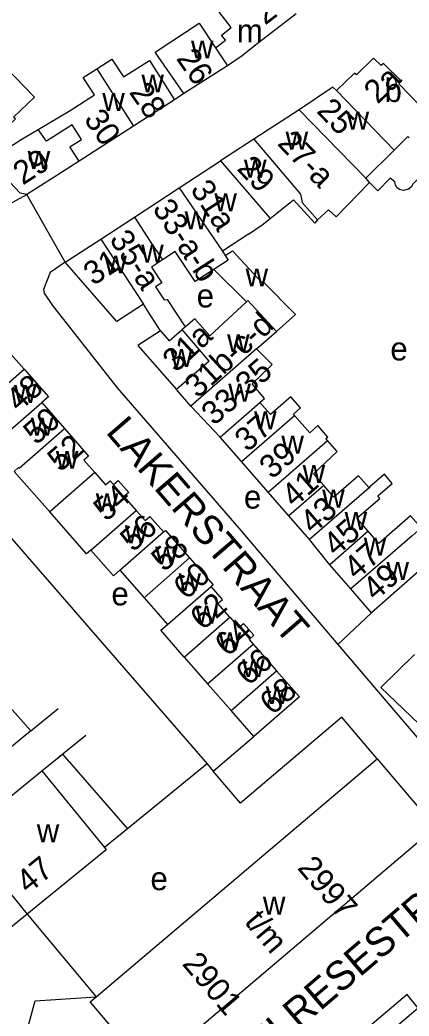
# Model space of a CAD drawing. Extents: x 161775 to 163181, y 382878 to 383925.
# Drawn here: x 162245.9 to 162312.7, y 383208.3 to 383379.1 of the extents above; entities that cross this region are included whole.
import ezdxf

# ---------------------------------------------------------------- set-up
doc = ezdxf.new("R2010")
doc.units = 0
for name, color, linetype in [('BLT_Basislijn', 7, 'Continuous'), ('BLT_Bebouwing', 7, 'Continuous'), ('BLT_Centroide', 7, 'Continuous'), ('BLT_Huisnummer', 7, 'Continuous'), ('BLT_Huisnummer_ tussenligend', 7, 'Continuous'), ('BLT_Huisnummer_reeks', 7, 'Continuous'), ('BLT_Onderdoorgang_en_onderverdeling', 7, 'Continuous'), ('BLT_Onderverdeling_panden', 7, 'Continuous'), ('BLT_Straatnaam', 7, 'Continuous'), ('BLT_Vlakafsluiter', 7, 'Continuous')]:
    doc.layers.add(name, color=color, linetype=linetype)

msp = doc.modelspace()

# ---------------------------------------------------------------- linework, layer by layer
at = {"layer": 'BLT_Basislijn'}
for p, q in [((162274.06, 383366.49), (162272.47, 383365.4)), ((162300.43, 383272.05), (162306.21, 383277.49)), ((162247.8, 383257.21), (162252.5, 383261.05)), ((162252.51, 383252.64), (162257.22, 383256.48)), ((162278.02, 383251.56), (162264.39, 383240.46)), ((162278.02, 383251.56), (162279.09, 383250.32)), ((162264.39, 383240.46), (162260.42, 383237.22)), ((162247.18, 383225.8), (162259, 383211.62)), ((162312.32, 383212.02), (162272.82, 383178.64)), ((162314.2, 383209.68), (162312.32, 383212.02))]:
    msp.add_line(p, q, dxfattribs=at)
for points in [[(162241.27, 383346.24), (162242.36, 383346.62), (162247.15, 383349.17)], [(162253.7, 383337.55), (162251.13, 383335.8), (162249.98, 383332.89), (162250.1, 383332.26), (162251.55, 383330.16), (162262.59, 383316.03), (162283.5, 383291.98), (162300.43, 383272.05)], [(162241.86, 383293.15), (162278.02, 383251.56)], [(162227.26, 383280.38), (162247.8, 383257.21), (162241.18, 383251.81)], [(162300.43, 383272.05), (162323.97, 383244.46)], [(162307.2, 383252.45), (162301.12, 383259.55), (162283.78, 383244.81), (162279.09, 383250.32)], [(162279.09, 383250.32), (162286.06, 383256.24)], [(162249.73, 383250.39), (162253.26, 383253.25), (162264.39, 383240.46)]]:
    msp.add_lwpolyline(points, dxfattribs=at)
at = {"layer": 'BLT_Bebouwing'}
for p, q in [((162293.29, 383380.14), (162286.12, 383374.58)), ((162281.53, 383371.21), (162274.06, 383366.49)), ((162272.47, 383365.4), (162265.43, 383360.89)), ((162249.08, 383360.32), (162254.56, 383363.57)), ((162293.82, 383363.71), (162286.05, 383358.64)), ((162246.15, 383358.59), (162249.08, 383360.32)), ((162265.43, 383360.89), (162256.1, 383354.91)), ((162286.05, 383358.64), (162280.33, 383354.92)), ((162256.1, 383354.91), (162251.81, 383352.16)), ((162273.27, 383350.29), (162280.33, 383354.92)), ((162251.81, 383352.16), (162247.15, 383349.17)), ((162265.58, 383345.31), (162273.27, 383350.29)), ((162288.84, 383345.07), (162292.85, 383348.27)), ((162259.8, 383341.54), (162265.58, 383345.31)), ((162253.7, 383337.55), (162259.8, 383341.54)), ((162280.65, 383339.45), (162281.14, 383338.7)), ((162279.17, 383336.33), (162284.77, 383330.79)), ((162286.53, 383322.73), (162289.92, 383325.69)), ((162275.26, 383312.91), (162272.8, 383315.72)), ((162280.28, 383307.57), (162275.26, 383312.91)), ((162283.94, 383303.38), (162280.28, 383307.57)), ((162292.03, 383294.09), (162288.48, 383298.17)), ((162295.57, 383290.02), (162292.03, 383294.09)), ((162299.05, 383285.69), (162295.57, 383290.02)), ((162263.08, 383284.79), (162267.25, 383280.04)), ((162302.65, 383281.58), (162299.05, 383285.69)), ((162314.8, 383284.99), (162306.21, 383277.49)), ((162306.21, 383277.49), (162302.65, 383281.58)), ((162267.25, 383280.04), (162271.25, 383275.45)), ((162285.92, 383272.12), (162289.95, 383267.54)), ((162274.13, 383269.89), (162278.13, 383265.31)), ((162278.13, 383265.31), (162282.15, 383260.72))]:
    msp.add_line(p, q, dxfattribs=at)
for points in [[(162279.49, 383374.32), (162281.2, 383375.64), (162280.52, 383376.51), (162282.18, 383377.8), (162280.05, 383380.56), (162281.1, 383381.37)], [(162274.06, 383366.49), (162271.2, 383370.6), (162269.13, 383373.57), (162276.67, 383378.53), (162279.49, 383374.32)], [(162286.12, 383374.58), (162284.04, 383372.97), (162281.53, 383371.21)], [(162259.14, 383370.71), (162261.73, 383372.37), (162263.69, 383369.32), (162268.14, 383372.17), (162269.78, 383369.61), (162272.47, 383365.4)], [(162316.35, 383362.57), (162310.93, 383368.14), (162311.36, 383368.61), (162308.3, 383371.65), (162307.88, 383371.27), (162306.56, 383372.55), (162303.62, 383369.69), (162303.29, 383369.98), (162300.19, 383366.98)], [(162239.26, 383356.45), (162242.87, 383359.92), (162245.17, 383362.12), (162244.85, 383362.45), (162248.42, 383365.88), (162243.44, 383371.07), (162237.57, 383365.43), (162233.96, 383361.97)], [(162254.56, 383363.57), (162258.71, 383366.23), (162256.8, 383369.21), (162259.14, 383370.71)], [(162300.19, 383366.98), (162299.59, 383367.55), (162293.82, 383363.71)], [(162240.63, 383355.05), (162244.84, 383357.75), (162246.15, 383358.59)], [(162247.15, 383349.17), (162245.99, 383349.43), (162240.63, 383355.05)], [(162305.87, 383351.23), (162300.17, 383345.35), (162298.84, 383346.53), (162296.98, 383344.82)], [(162317.01, 383348.74), (162314.07, 383351.71), (162313.22, 383350.87), (162313.05, 383350.5), (162312.54, 383350.07), (162311.7, 383349.86), (162311.01, 383350.02), (162310.54, 383350.39), (162310.33, 383350.78), (162310.19, 383351.32), (162309.44, 383352), (162307.32, 383349.81), (162305.87, 383351.23)], [(162296.98, 383344.82), (162296.48, 383344.27), (162292.85, 383348.27)], [(162265.58, 383345.31), (162268.29, 383341.12), (162270.36, 383337.95)], [(162285.11, 383342.38), (162287.49, 383343.99), (162288.84, 383345.07)], [(162285.11, 383342.38), (162280.65, 383339.45)], [(162279.17, 383336.33), (162276.01, 383334.26), (162272.57, 383339.39), (162270.36, 383337.95)], [(162281.14, 383338.7), (162282.36, 383339.52), (162287.4, 383334.08), (162287.6, 383334.28), (162293.2, 383328.6), (162289.92, 383325.69)], [(162267.12, 383330.35), (162262.57, 383327.4), (162253.7, 383337.55)], [(162270.36, 383337.95), (162268.48, 383336.72), (162270.28, 383334.02), (162269.2, 383333.32), (162270.66, 383331.13), (162271.25, 383331.17)], [(162267.97, 383329.03), (162267.12, 383330.35)], [(162274.34, 383326.47), (162271.25, 383331.17)], [(162284.77, 383330.79), (162278.51, 383324.92), (162275.95, 383327.87), (162274.34, 383326.47)], [(162270.07, 383325.79), (162267.97, 383329.03)], [(162270.07, 383325.79), (162266.18, 383323.27), (162272.8, 383315.72)], [(162242.64, 383323.81), (162246.69, 383319.24)], [(162287.1, 383313.52), (162287.9, 383314.22), (162285.74, 383316.69), (162289.17, 383320.01), (162286.53, 383322.73)], [(162246.69, 383319.24), (162250.83, 383314.49), (162249.7, 383313.51)], [(162249.7, 383313.51), (162253.58, 383309.08)], [(162293.04, 383311.3), (162292.84, 383311.53), (162294.04, 383312.58), (162292.39, 383314.48), (162288.91, 383311.44), (162287.1, 383313.52)], [(162298.41, 383307.33), (162298.73, 383307.6), (162297.03, 383309.55), (162295.63, 383308.33), (162293.04, 383311.3)], [(162253.58, 383309.08), (162257.73, 383304.34), (162256.92, 383303.62), (162258.77, 383301.51)], [(162298.02, 383299.3), (162296.28, 383301.3), (162300.33, 383305.12), (162298.66, 383307.03)], [(162298.66, 383307.03), (162298.41, 383307.33)], [(162288.48, 383298.17), (162284.7, 383302.52), (162283.94, 383303.38)], [(162251.05, 383294.75), (162244.97, 383301.71), (162245.71, 383302.36)], [(162258.77, 383301.51), (162260.62, 383299.4), (162261.43, 383300.1), (162262, 383299.45), (162262.8, 383300.15), (162264.59, 383298.11), (162263.78, 383297.4), (162265.88, 383295.03)], [(162305.79, 383298.91), (162303.99, 383300.97), (162299.77, 383297.29), (162298.02, 383299.3)], [(162305.67, 383291.44), (162303.73, 383293.67), (162307.66, 383297.08), (162307.29, 383297.5), (162309.77, 383299.66), (162308.42, 383301.21), (162305.95, 383299.05), (162305.79, 383298.91)], [(162258.1, 383288.21), (162257.35, 383287.55), (162251.05, 383294.75)], [(162265.88, 383295.03), (162267.42, 383293.27), (162268.22, 383293.98), (162270.55, 383291.32)], [(162313.19, 383290.69), (162314.72, 383292.01), (162312.91, 383294.1), (162307.48, 383289.37), (162305.67, 383291.44)], [(162270.55, 383291.32), (162270.88, 383291.6), (162275, 383286.89)], [(162258.1, 383288.21), (162261.96, 383283.81), (162263.08, 383284.79)], [(162275, 383286.89), (162279.05, 383282.27), (162278.74, 383281.99)], [(162281.94, 383276.72), (162279.86, 383279.07), (162280.67, 383279.77), (162278.74, 383281.99)], [(162281.94, 383276.72), (162283.46, 383274.96), (162284.27, 383275.66), (162286.04, 383273.61), (162285.23, 383272.91), (162285.92, 383272.12)], [(162274.13, 383269.89), (162270.13, 383274.47), (162271.25, 383275.45)], [(162313.56, 383270.3), (162307.79, 383264.65), (162320.87, 383252.21), (162325.95, 383257.24)], [(162289.95, 383267.54), (162293.86, 383263.09), (162286.06, 383256.24)], [(162286.06, 383256.24), (162282.15, 383260.72)], [(162259, 383211.62), (162307.2, 383252.45)], [(162307.2, 383252.45), (162317.2, 383240.64)], [(162236.17, 383239.36), (162249.73, 383250.39)], [(162249.73, 383250.39), (162260.42, 383237.22)], [(162317.2, 383240.64), (162268.02, 383198.98), (162258.01, 383210.79), (162259, 383211.62)], [(162260.75, 383236.82), (162247.18, 383225.8)], [(162260.42, 383237.22), (162260.75, 383236.82)], [(162247.18, 383225.8), (162234.74, 383215.7)], [(162314.2, 383209.68), (162309.63, 383205.82)]]:
    msp.add_lwpolyline(points, dxfattribs=at)
at = {"layer": 'BLT_Onderdoorgang_en_onderverdeling'}
msp.add_line((162236.17, 383239.36), (162247.18, 383225.8), dxfattribs=at)
msp.add_lwpolyline([(162280.33, 383354.92), (162288.84, 383345.07)], dxfattribs=at)
at = {"layer": 'BLT_Onderverdeling_panden'}
for p, q in [((162279.49, 383374.32), (162281.53, 383371.21)), ((162259.14, 383370.71), (162265.43, 383360.89)), ((162300.19, 383366.98), (162310.09, 383356.78)), ((162293.82, 383363.71), (162305.26, 383351.99)), ((162305.26, 383351.99), (162310.09, 383356.78)), ((162305.87, 383351.23), (162305.26, 383351.99)), ((162273.27, 383350.29), (162280.65, 383339.45)), ((162259.8, 383341.54), (162267.12, 383330.35)), ((162284.99, 383330.99), (162284.77, 383330.79)), ((162289.92, 383325.69), (162284.99, 383330.99)), ((162274.34, 383326.47), (162273.77, 383326.03)), ((162278.4, 383320.59), (162273.77, 383326.03)), ((162278.4, 383320.59), (162272.8, 383315.72)), ((162238.88, 383312.42), (162246.69, 383319.24)), ((162280.28, 383307.57), (162287.1, 383313.52)), ((162283.94, 383303.38), (162293.04, 383311.3)), ((162288.48, 383298.17), (162298.66, 383307.03)), ((162258.77, 383301.51), (162251.05, 383294.75)), ((162298.02, 383299.3), (162292.03, 383294.09)), ((162305.79, 383298.91), (162295.57, 383290.02)), ((162258.1, 383288.21), (162265.88, 383295.03)), ((162263.08, 383284.79), (162270.55, 383291.32)), ((162305.67, 383291.44), (162299.05, 383285.69)), ((162313.19, 383290.69), (162302.65, 383281.58)), ((162267.25, 383280.04), (162275, 383286.89)), ((162274.13, 383269.89), (162281.94, 383276.72)), ((162278.13, 383265.31), (162285.92, 383272.12)), ((162282.15, 383260.72), (162289.95, 383267.54))]:
    msp.add_line(p, q, dxfattribs=at)
for points in [[(162256.1, 383354.91), (162254.52, 383357.37), (162256.48, 383358.62), (162254.9, 383361.1), (162250.48, 383358.32), (162249.08, 383360.32)], [(162286.05, 383358.64), (162294.06, 383349.23), (162294.32, 383347.81), (162296.98, 383344.82)], [(162312.66, 383358.89), (162312.45, 383359.11), (162310.09, 383356.78)], [(162281.14, 383338.7), (162281.63, 383337.94), (162279.17, 383336.33)], [(162270.07, 383325.79), (162271.52, 383324.11), (162273.77, 383326.03)], [(162286.53, 383322.73), (162275.26, 383312.91)], [(162243.03, 383307.68), (162249.7, 383313.51)], [(162245.71, 383302.36), (162245.79, 383302.26), (162253.58, 383309.08)], [(162271.25, 383275.45), (162278.74, 383281.99)]]:
    msp.add_lwpolyline(points, dxfattribs=at)
at = {"layer": 'BLT_Vlakafsluiter'}
msp.add_line((162253.7, 383337.55), (162247.15, 383349.17), dxfattribs=at)
msp.add_lwpolyline([(162246.05, 383201.76), (162248.57, 383210.98), (162259, 383211.62)], dxfattribs=at)

# ---------------------------------------------------------------- texts
at = {"layer": 'BLT_Centroide'}
for s, p in [('m', (162283.14, 383375.24)), ('w', (162275.27, 383372.5)), ('w', (162266.78, 383366.66)), ('b', (162308.45, 383365.03)), ('w', (162260.06, 383363.5)), ('w', (162301.95, 383360.3)), ('w', (162291.49, 383356.85)), ('w', (162247.27, 383353.55)), ('w', (162284.36, 383352.05)), ('w', (162279.28, 383346.3)), ('w', (162274.19, 383343.2)), ('w', (162266.73, 383337.5)), ('w', (162260.42, 383335.64)), ('w', (162284.63, 383333.41)), ('e', (162276.24, 383329.82)), ('w', (162281.46, 383322.16)), ('e', (162309.45, 383320.73)), ('w', (162271.71, 383319.61)), ('w', (162281.67, 383313.66)), ('w', (162244.93, 383313.44)), ('w', (162286.08, 383308.94)), ('w', (162247.82, 383307.84)), ('w', (162290.77, 383304.75)), ('w', (162252.1, 383302.16)), ('w', (162294.41, 383299.73)), ('w', (162258.95, 383294.88)), ('e', (162284.35, 383295.33)), ('w', (162297.76, 383295.5)), ('w', (162301.61, 383291.66)), ('w', (162263.94, 383289.38)), ('w', (162304.89, 383287.28)), ('w', (162269.13, 383285.75)), ('w', (162308.78, 383283.11)), ('w', (162273.13, 383281.19)), ('e', (162261.63, 383278.74)), ('w', (162276.01, 383275.62)), ('w', (162280.02, 383271.03)), ('w', (162284.04, 383266.44)), ('w', (162288.09, 383261.81)), ('w', (162248.84, 383238.15)), ('e', (162268.32, 383229.92)), ('w', (162287.6, 383225.72))]:
    msp.add_text(s, height=4, dxfattribs=at).set_placement(p)
at = {"layer": 'BLT_Huisnummer'}
for s, rotation, p in [('24', 37.7653, (162287.98, 383378.1)), ('26', 304.8343, (162272.63, 383372.47)), ('2a', 43.9937, (162307.27, 383364.56)), ('28', 304.8343, (162264.56, 383366.68)), ('25', 313.9937, (162296.65, 383363.36)), ('30', 304.8343, (162256.8, 383362.07)), ('29', 32.6471, (162246.44, 383350.7)), ('29', 313.9937, (162282.97, 383353.49)), ('31a', 302.9182, (162275.06, 383350.06)), ('31', 32.9073, (162258.52, 383333.45)), ('31a', 42.7632, (162272.69, 383318.52)), ('48', 41.1671, (162245.74, 383311.75)), ('37', 41.1001, (162284.95, 383304.9)), ('52', 41.1671, (162252.85, 383301.46)), ('41', 41.0163, (162292.96, 383295.38)), ('56', 41.5556, (162265.34, 383287.76)), ('45', 41.0277, (162300.11, 383286.98)), ('60', 41.1671, (162274.44, 383279.57)), ('49', 41.2923, (162306.88, 383279.35)), ('64', 41.1671, (162281.53, 383269.82)), ('68', 41.1671, (162289.24, 383259.79))]:
    msp.add_text(s, height=4, rotation=rotation, dxfattribs=at).set_placement(p)
at = {"layer": 'BLT_Huisnummer_ tussenligend'}
for s, rotation, p in [('50', 41.1671, (162248.72, 383306.1)), ('39', 41.1001, (162289.17, 383300.23)), ('54', 41.1671, (162260.74, 383292.98)), ('43', 41.0163, (162296.14, 383290.81)), ('58', 41.1671, (162270.65, 383284.36)), ('47', 41.0277, (162303.62, 383282.95)), ('62', 41.1671, (162277.3, 383274.33)), ('66', 41.1671, (162285.13, 383264.82))]:
    msp.add_text(s, height=4, rotation=rotation, dxfattribs=at).set_placement(p)
at = {"layer": 'BLT_Huisnummer_reeks'}
for s, rotation, p in [('27-a', 313.9937, (162289.92, 383357.78)), ('33-a-b', 302.9182, (162268.56, 383346.78)), ('35-a', 302.6013, (162261.18, 383341.5)), ('31b-c-d', 42.7632, (162276.45, 383314.1)), ('33-35', 41.1013, (162279.23, 383309.42)), ('47', 39.063, (162247.35, 383229.17)), ('2997', 310.2651, (162293.37, 383233.68)), ('t/m', 310.2651, (162284.29, 383224.43)), ('2901', 310.2651, (162273.62, 383217.23))]:
    msp.add_text(s, height=4, rotation=rotation, dxfattribs=at).set_placement(p)
at = {"layer": 'BLT_Straatnaam'}
for s, height, rotation, p in [('LAKERSTRAAT', 5, 310.7804, (162260.52, 383308.4)), ('TONGELRESESTRAAT', 4.9999, 40.4764, (162272.83, 383188.14))]:
    msp.add_text(s, height=height, rotation=rotation, dxfattribs=at).set_placement(p)

doc.saveas('drawing.dxf')
